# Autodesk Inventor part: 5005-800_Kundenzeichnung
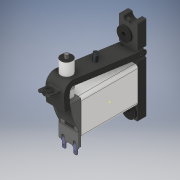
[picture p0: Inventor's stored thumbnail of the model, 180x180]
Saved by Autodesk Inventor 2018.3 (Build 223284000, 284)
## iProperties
Created: 2023-02
Part Number: 5005-800_Kundenzeichnung
Material: Generisch
Document SubType Name: Modeling
Designer: T.Heuss
Density: 1 g/cm^3
Appearance: Vorgabe
Author: T.Heuss
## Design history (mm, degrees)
derived "5005-600.iam"
node "Volumenkörper1"
node "Gundplatte 5005-811:1"
node "5005-830_Kern.ipt:1"
node "Skizze3"
node "5005-104_Messingbuchse.ipt:1"
node "5005820_Anker Vormontiert.iam:1::2037-000_Plastiklinse.ipt:1"
node "5005820_Anker Vormontiert.iam:1::5005-821_Anker.ipt:1"
node "5005820_Anker Vormontiert.iam:1::5005-825_Federhalter.ipt:1"
node "5005-841_Spulenkörper.iam:1::18_024_Artikel.ipt:1"
node "5005-841_Spulenkörper.iam:1::5005-845_Gewindebolzen.ipt:1"
node "5005-840_Spulenhülse ohne druck.ipt:1"
sketch "Skizze4"
  geometry: 1 further point
node "BS EN 28734 A - ersetzt durch BS EN ISO 8734 2,5 x 16 - A:1"
node "5001-128.ipt:1"
node "5001-128.ipt:2"
node "5001-123.ipt:1"
node "5011-115.ipt:1"
node "5011-115.ipt:2"
